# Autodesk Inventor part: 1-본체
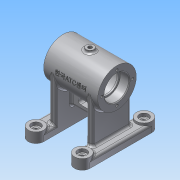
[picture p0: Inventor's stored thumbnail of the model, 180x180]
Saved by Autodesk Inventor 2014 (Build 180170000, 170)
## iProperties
Created: 2015-11
Part Number: 1-본체
Material: 알루미늄 6061
Document SubType Name: Modeling
Designer: 702
Density: 2.71 g/cm^3
Appearance: 알루미늄 - 평지
Mass: 358.848 g
Surface Area: 454.549 cm^2
Volume: 132.416 cm^3
Author: 702
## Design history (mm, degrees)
sketch "스케치1"
  geometry: L1 (-40, -30)-(40, -30); L2 (40, -30)-(40, 30); L3 (40, 30)-(-40, 30); L4 (-40, 30)-(-40, -30); L5 (-40, -30)-(40, 30); L6 (40, -30)-(-40, 30); L7 (-40, 20)-(40, 20); L8 (-40, 40)-(40, 40); L9 (-40, -20)-(40, -20); L10 (-40, -40)-(40, -40); L11 (-4, 20)-(4, 20); L12 (4, 20)-(4, -20); L13 (4, -20)-(-4, -20); L14 (-4, -20)-(-4, 20); L15 (-4, 20)-(4, -20); L16 (4, 20)-(-4, -20); A1 r 10 centre (-40, 30) between (-40, 20) and (-40, 40); A2 r 10 centre (40, 30) between (40, 20) and (40, 40); A3 r 10 centre (-40, -30) between (-40, -20) and (-40, -40); A4 r 10 centre (40, -30) between (40, -20) and (40, -40); 1 further point
  constraints: 32 end point, 8 point on circle, 5 parallel, 4 centre point, 4 coincident, 4 midpoint, 3 equal radius, 3 perpendicular, 3 point on line, 3 tangent, 2 horizontal, 1 collinear
  dimensions: "d0" = 80 distance of L2.end L3.end; "d1" = 60 distance of L1.end L2.end; "d2" = 20 diameter of A1; "d3" = 8 distance of L11.start L11.end
extrude "돌출1" new body sketch "스케치1" distance "d4" = 10; taper "d5" = 0 deg
extrude "돌출2" join sketch "스케치1" distance "d6" = 13; taper "d7" = 0 deg
sketch "스케치2"
  geometry: L1 (0, 0)-(0, 68); C1 r 25 at (0, 68)
  constraints: 2 end point, 1 centre point, 1 coincident, 1 vertical
  dimensions: "d8" = 68 distance of L1.start L1.end; "d9" = 50 diameter of C1
extrude "돌출3" join sketch "스케치2" stored distance "d10" = 70; taper "d11" = 0 deg
sketch "스케치3"
  geometry: L1 (40, -20)-(-40, -20) reference; L2 (-25, -28)-(25, -28); L3 (25, -28)-(25, -20); L4 (25, -20)-(-25, -20); L5 (-25, -20)-(-25, -28); L6 (40, -20)-(-40, -20) reference; L7 (0, 0)-(46.4, 0); L8 (-25, 28)-(25, 28); L9 (25, 28)-(25, 20); L10 (25, 20)-(-25, 20); L11 (-25, 20)-(-25, 28); 2 further points
  constraints: 18 end point, 5 symmetric about line, 3 parallel, 2 midpoint, 1 horizontal, 1 perpendicular
  dimensions: "d12" = 8 distance of L2.end L3.end; "d13" = 50 distance of L2.start L2.end
extrude "돌출4" join sketch "스케치3" stored distance "d14" = 70; taper "d15" = 0 deg
sketch "스케치4"
  geometry: L1 (-35, 48)-(35, 48); L2 (-22.5, 23)-(22.5, 23); L3 (22.5, 23)-(22.5, 48); L4 (22.5, 48)-(-22.5, 48); L5 (-22.5, 48)-(-22.5, 23); L6 (-20, 0)-(-40, 0) reference; 2 further points
  constraints: 10 end point, 2 midpoint, 1 horizontal, 1 parallel, 1 perpendicular
  dimensions: "d18" = 45 distance of L2.start L2.end; "d64" = 23 distance between parallel lines of L6 L2; "d65" = 25 distance of L4.end L2.start
extrude "돌출5" join sketch "스케치4" stored distance "d19" = 8; taper "d20" = 0 deg
sketch "스케치5"
  geometry: L1 (-23, -20)-(-23, 20) reference; L2 (0, 0)-(-33, 0); L3 (-33, 11.5)-(-33, -8); L4 (-36.5, -8)-(-36.5, 8); L5 (-29.5, -8)-(-29.5, 8); A1 r 3.5 centre (-33, 8) between (-36.5, 8) and (-29.5, 8); A2 r 3.5 centre (-33, -8) between (-36.5, -8) and (-29.5, -8)
  constraints: 8 end point, 5 point on circle, 3 tangent, 2 centre point, 2 perpendicular, 2 point on line, 1 coincident, 1 equal radius, 1 parallel, 1 vertical alignment
  dimensions: "d21" = 33 distance of L2.end L2.start; "d22" = 7 diameter of A1; "d23" = 23 dimension on A1 A2
extrude "돌출6" cut sketch "스케치5" stored distance "d24" = 8; taper "d25" = 0 deg
sketch "스케치6"
  geometry: C1 r 10 at (0, 0) reference; 1 further point
hole "구멍1" sketch "스케치6" at (0, 0) diameter "d26" = 6; stored, may be unused: countersink angle "d30" = 90 deg, drill point angle "d32" = 118 deg; dims "d27" = 6, "d28" = 12, "d29" = 4, "d31" = 8
fillet "모깎기1" dims "d33" = 0.3
chamfer "모따기1" distance "d34" = 1; stored, may be unused: second distance "d35" = 2, angle "d36" = 45 deg
sketch "스케치7"
  geometry: C1 r 25 at (0, 0) reference; 1 further point
hole "구멍2" sketch "스케치7" at (0, 0) diameter "d37" = 28; stored, may be unused: countersink angle "d41" = 90 deg, drill point angle "d43" = 118 deg; dims "d38" = 6, "d39" = 32, "d40" = 12, "d42" = 8
sketch "스케치8"
  geometry: C1 r 14 at (0, 68) reference; C2 r 21 at (0, 68); 1 further point
  constraints: 1 centre point, 1 coincident
  dimensions: "d44" = 42 diameter of C2
extrude "돌출7" cut sketch "스케치8" stored distance "d45" = 42; taper "d46" = 0 deg
sketch "스케치9"
  geometry: L1 (-21, 89)-(21, 89) reference; L2 (-35, 93)-(35, 93) reference; L3 (35, 43)-(35, 93) reference; L4 (-35, 93)-(-35, 43) reference; L5 (0, 89)-(5, 89); L6 (5, 89)-(5, 96); L7 (5, 96)-(0, 96); L8 (0, 96)-(0, 89); 1 further point
  constraints: 8 end point, 2 parallel, 1 collinear, 1 horizontal, 1 perpendicular
  dimensions: "d48" = 5 distance of L6.end L7.end; "d49" = 35 distance between parallel lines of L3 L8; "d50" = 3 distance between parallel lines of L2 L7
revolve "회전1" sketch "스케치9" stored, may be unused: angle "d51" = 90 deg
sketch "스케치10" dims "d52" = 40
  geometry: C1 r 25 at (0, 0) reference; 3 further points
  constraints: 1 coincident, 1 vertical alignment, 2 other
hole "구멍3" sketch "스케치10" at (0, -20) diameter "d53" = 3.242; stored, may be unused: countersink angle "d57" = 90 deg, drill point angle "d59" = 118 deg; dims "d54" = 8, "d55" = 4, "d56" = 2, "d58" = 10
fillet "모깎기2" dims "d66" = 3
fillet "모깎기3" dims "d67" = 3
fillet "모깎기4" dims "d68" = 3
chamfer "모따기2" distance "d69" = 1; stored, may be unused: second distance "d70" = 2, angle "d71" = 45 deg
fillet "모깎기5" dims "d72" = 0.3, "d73" = 3
sketch "스케치11"
  geometry: A1 r 5 centre (0, 0) between (0, -5) and (0, 5) reference; A2 r 5 centre (0, 0) between (0, 5) and (0, -5) reference
hole "구멍4" sketch "스케치11" at (0, 0) diameter "d74" = 4.917; stored, may be unused: countersink angle "d78" = 90 deg, drill point angle "d80" = 118 deg; dims "d75" = 8, "d76" = 4, "d77" = 2, "d79" = 10
sketch "스케치12"
  geometry: L1 (0, 68)-(0, 22.904); L2 (41.832, 68)-(76.847, 68); L3 (76.847, 68)-(76.847, 60.104); L4 (76.847, 60.104)-(41.832, 60.104); L5 (41.832, 60.104)-(41.832, 68); L6 (14, 43.751)-(8.804, 40.751); L7 (11.305, 48.42)-(14, 43.751); L8 (5.703, 46.122)-(8.804, 40.751); C1 r 14 at (0, 68) reference; A1 r 22.609 centre (0, 68) between (5.703, 46.122) and (11.305, 48.42); 1 further point
  constraints: 16 end point, 2 parallel, 2 perpendicular, 2 point on circle, 1 centre point, 1 coincident, 1 horizontal, 1 vertical
  dimensions: "d82" = 28 distance of L1.start L6.start; "d84" = 6 distance between parallel lines of L7 L8
revolve "회전2" sketch "스케치12" stored, may be unused: angle "d85" = 90 deg
fillet "모깎기6" dims "d86" = 3
sketch "스케치13"
  geometry: A1 r 6 centre (0, 0) between (0, 6) and (0, -6) reference; 1 further point
hole "구멍5" sketch "스케치13" at (0, 0) diameter "d87" = 4.917; stored, may be unused: countersink angle "d91" = 90 deg, drill point angle "d93" = 118 deg; dims "d88" = 8, "d89" = 4, "d90" = 2, "d92" = 10
node "작업 평면1"
sketch "스케치14"
  geometry: L1 (-5, 96)-(5, 96) reference; 3 further points
  constraints: 1 midpoint, 1 vertical alignment, 1 other
  dimensions: "d95" = 25 distance of point (0, 96) point (0, 71)
feature "엠보싱1" sketch "스케치14" dims "d0" = 80, "d1" = 60, "d2" = 20, "d3" = 8, "d96" = 0.5, "d97" = 0
node "솔리드1"
mirror "대칭1"
mirror "대칭2"
mirror "대칭3"
pattern_circular "원형 패턴1" dims angle "d61" = 360 deg
mirror "대칭4"
other parameters: "d81" = 30 deg, "d83" = 6, "d94" = 25
